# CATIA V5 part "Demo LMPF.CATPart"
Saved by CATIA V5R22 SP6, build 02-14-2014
Part number: Demo AM
Bounding box of the stored display mesh (mm): x -38 to 38, y -38 to 38, z -6.84 to 26.244
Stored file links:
  C:\Users\kremer\Desktop\demo_5x\Demo LMPF.CATPart
  Y:\piece divers\caddy\logo_AM.CATPart
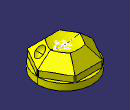
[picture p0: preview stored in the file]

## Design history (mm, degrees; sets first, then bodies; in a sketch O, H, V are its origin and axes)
AxisSystem1: origin (0, 0, 0), X (1, 0, 0), Y (0, 1, 0), Z (0, 0, 1)
Set1
  Plane1: type Angle, RefPlane face of Pocket1 from Sketch2.L1, Direction edge [face of Pocket1 from Sketch2.L1 | end face of Pad1], Angle 45
  Plane2: type Angle, RefPlane face of CircPattern1, Direction Sketch9, Angle 90
  Point1: (0, 0, 80), in AxisSystem1
  Sphere1: Center Point1, Axis AxisSystem1, Radius 57.5, Angle1 -90, Angle3 0, Angle4 360
  MultiSel1
Body1 (main body)
  Sketch1 on XY plane of AxisSystem1, origin (0, 0, 0), H (1, 0, 0), V (0, 1, 0)
    circle A1 centre (0, 0) radius 50
    radius A1 = 50
  Pad1: profile Sketch1, direction (0, 0, 1), length 35, opposite side length 9
  Sketch2 on end face of Pad1, origin (0, 0, 35), H (1, 0, 0), V (0, 1, 0)
    point P1 (25.4034, 44)
    point P2 (-25.4034, 44)
    point P3 (-50.8068, 0)
    point P4 (-25.4034, -44)
    point P5 (25.4034, -44)
    point P6 (50.8068, 0)
    point P7 (0, 44)
    line L1 (25.4034, 44) -> (-25.4034, 44)
    line L2 (-25.4034, 44) -> (-50.8068, 0)
    line L3 (-50.8068, 0) -> (-25.4034, -44)
    line L4 (-25.4034, -44) -> (25.4034, -44)
    line L5 (25.4034, -44) -> (50.8068, 0)
    line L6 (50.8068, 0) -> (25.4034, 44)
    construction line L7 (0, 0) -> (0, 44)
    construction circle A1 centre (0, 0) radius 50.8068
    construction arc A2 centre (25.4034, -44) radius 50.8068 from (-25.4034, -44) to (50.8068, 0) cw
    construction arc A3 centre (-25.4034, 44) radius 50.8068 from (-50.8068, 0) to (25.4034, 44) ccw
    length L7 = 44
    vertical: L7 V
    coincidence: A1 P1, A1 P2, A1 P3, A1 P4, A1 P5, A1 P6, A2 O, A3 O
    midpoint: P7 L1
    parallelism: L1 L4
  Pocket1: profile Sketch2, direction (0, 0, -1), length 32, outer side
  Sketch3 on Plane1, origin (0, 50.6879, 28.3121), H (1, 0, 0), V (0, -0.7071, 0.7071)
    point P1 (0, 7.5)
    line L1 (56.2227, 27) -> (56.2227, -12)
    line L2 (56.2227, -12) -> (-56.2227, -12)
    line L3 (-56.2227, -12) -> (-56.2227, 27)
    line L4 (-56.2227, 27) -> (56.2227, 27)
    distance H L2 = 12
    distance H L4 = 27
    coincidence: P1 V
    vertical: L1 V, L3 V
    horizontal: L2 H, L4 H
    equidistance: L1 L3 P1, L2 L4 P1
  Pocket2: profile Sketch3, direction (0, -0.7071, -0.7071), length 15
  CircPattern1: of Pocket2, instances 6, angular step 60 {= 360.0*1 deg/CircPattern1.AngularNumber}, axis from XY plane of AxisSystem1
  Sketch4 on end face of Pocket2, origin (0, 28.8934, 28.8934), H (-1, 0, 0), V (0, -0.7071, 0.7071)
    circle A1 centre (0, -6.364) radius 11
    point P1 (0, -6.364)
    reference projected line E1 through (0, 0) direction (0, -1) from edge [YZ plane of AxisSystem1 | XY plane of AxisSystem1]
    reference projected line E2 (37.6887, 8.636) -> (-37.6887, 8.636) from edge [end face of Pad1 | end face of Pocket2]
    radius A1 = 11
    distance P1 E2 = 15
    coincidence: P1 E1
  Pocket3: profile Sketch4, direction (0, -0.7071, -0.7071), length 6, deactivated
  Sketch5 on face of CircPattern1, origin (-25.0224, -14.4467, 28.8934), H (0.5, -0.866, 0), V (0.6124, 0.3536, 0.7071)
    line L1 (-8.6038, 0.6201) -> (-11.1038, -3.7101)
    line L2 (8.6599, 0.523) -> (11.1599, -3.8071)
    line L3 (-2.5004, -18.8071) -> (2.4996, -18.8071)
    construction circle A1 centre (0, -7.364) radius 11.4432
    point P7 (0, -7.364)
    arc A2 centre (-0.0004, -4.477) radius 10 from (-8.6038, 0.6201) to (8.6599, 0.523) cw
    arc A3 centre (2.4996, -8.8071) radius 10 from (11.1599, -3.8071) to (2.4996, -18.8071) cw
    arc A4 centre (-2.5004, -8.8071) radius 10 from (-2.5004, -18.8071) to (-11.1038, -3.7101) cw
    reference projected line E1 (-13.156, 8.636) -> (13.156, 8.636) from edge [face of CircPattern1 | end face of Pad1]
    angle L2 L3 = 60
    angle L1 L3 = 60
    length L2 = 5
    length L1 = 5
    length L3 = 5
    radius A2 = 10
    radius A3 = 10
    radius A4 = 10
    distance P7 E1 = 16
    horizontal: L3 H
    tangency: A1 L2, L1 A1, A1 L3, A2 L2, A3 L2, A4 L3
    coincidence: P7 V
  Pocket4: profile Sketch5, direction (0.6124, 0.3536, -0.7071), length 3
  Scaling1: ToTransfor Pocket4, Reference vertex [YZ plane of AxisSystem1 | ZX plane of AxisSystem1 | XY plane of AxisSystem1], Ratio 0.76
  Sketch6 on start face of Pad1, origin (0, 0, -6.84), H (1, 0, 0), V (0, -1, 0)
    circle A1 centre (0, 0) radius 28
    radius A1 = 28
  Pocket5: profile Sketch6, direction (0, 0, 1), length 15
  Sketch7 on YZ plane of AxisSystem1, origin (0, 0, 0), H (0, 1, 0), V (0, 0, 1)
    line L1 (0, -6.84) -> (28, -6.84)
    point P1 (0, -6.84)
    line L2 (0, 8.16) -> (10, 8.16)
    point P3 (0, 8.16)
    arc A1 centre (10, -10.14) radius 18.3 from (28, -6.84) to (10, 8.16) ccw
    axis line L3 (0, 13.16) -> (0, -11.84)
    point P6 (0, 13.16)
    point P7 (0, -11.84)
    reference projected line E1 (-38, -6.84) -> (38, -6.84) from edge [start face of Pad1 | face of Pad1 from Sketch1.A1]
    length L1 = 28
    length L2 = 10
    distance L2 L1 = 15
    distance P7 L1 = 5
    distance P6 L2 = 5
    coincidence: P1 V, P3 V, P6 V, L1 E1
    horizontal: L1 H, L2 H
    tangency: A1 L2
    vertical: L3 V
  Groove1: profile Sketch7, axis Sketch7.L3, angle 360
  Sketch8 on Plane2, origin (3.2068, -1.8514, -3.7028), H (-0.5, -0.866, 0), V (0.6124, -0.3536, 0.7071)
    arc A1 centre (0, 33.0547) radius 8 from (0, 25.0547) to (7.746, 31.0547) ccw
    point P1 (0, 33.0547)
    point P2 (0, 25.0547)
    point P3 (7.746, 31.0547)
    axis line L1 (0, 14.857) -> (0, 47.7135)
    point P4 (0, 14.857)
    reference projected line E1 (-9.9985, 31.0547) -> (9.9985, 31.0547) from edge [end face of Pad1 | face of CircPattern1]
    reference projected line E2 (-9.9985, 31.0547) -> (9.9985, 31.0547) from edge [end face of Pad1 | face of CircPattern1]
    radius A1 = 8
    distance P1 E2 = 2
    coincidence: P1 V, P2 V, P4 V, P3 E1
    vertical: L1 V
  Groove2: profile Sketch8, axis Sketch8.L1, angle 360
  Sketch9 "( Axe Ref 1 ) Esquisse.30" on face of CircPattern1, origin (19.017, -10.9795, 21.959), H (0.5, 0.866, 0), V (-0.6124, 0.3536, 0.7071)
    line L1 (-58.589, -5.2366) -> (57.1551, -5.2366)
    reference projected line E1 (-18.049, -16.2366) -> (18.049, -16.2366) from edge [face of Pocket1 from Sketch2.L5 | face of CircPattern1]
    distance L1 E1 = 11
    horizontal: L1 H
  Split1: SplitPlane Sphere1
  Sketch10 "AM_contour ext" on xy-plane, origin (4.33, 0, 0), H (0, 1, 0), V (-1, 0, 0)
    construction line L1 (0, 60.7322) -> (0, -11.7377)
    point P17 (3.4248, 5.9688)
    point P19 (0, 15.8119)
    arc A1 centre (59.4869, -14.2774) radius 60.2195 from (0, -4.9132) to (1.5177, 2.0306) cw
    arc A2 centre (9.7654, 7.017) radius 9.6379 from (1.5177, 2.0306) to (5.3889, -1.5699) ccw
    arc A3 centre (-14.9238, 4.3682) radius 21.1629 from (5.3889, -1.5699) to (3.6441, -5.7856) cw
    arc A4 centre (-23.671, 8.3459) radius 31.4277 from (6.0559, -1.8526) to (4.0351, -6.489) cw
    spline S1 through (3.6458, -5.7858) (3.5931, -5.7699) (3.4911, -5.6186) (3.1628, -5.286) (2.82, -5.2669) (2.3716, -5.4882) (2.1874, -5.8327) (2.1242, -6.4187) (2.252, -6.8572) (2.4958, -7.1703) (2.7571, -7.3255) (3.1036, -7.3604) (3.4777, -7.1797) (3.823, -6.8205) (4.0351, -6.489)
    arc A5 centre (6.6749, 1.3247) radius 3.237 from (6.0559, -1.8526) to (9.9071, 1.5021) ccw
    spline S2 through (9.9065, 1.5017) (9.6533, 2.299) (8.894, 2.8422) (8.0588, 2.7385) (7.695, 2.4017) (7.379, 1.5027) (7.7109, 0.6261) (8.2591, 0.2442) (8.6579, 0.2441)
    arc A6 centre (-6.6766, 2.7131) radius 13.278 from (6.2511, -0.3165) to (5.5057, 7.9947) ccw
    arc A7 centre (9.9792, 2.4699) radius 8.4343 from (1.8858, 4.8435) to (3.5816, 7.9661) cw
    spline S3 through (3.5816, 7.9661) (3.8645, 8.2339) (4.3523, 8.4727) (4.7949, 8.4722) (5.303, 8.2673) (5.5057, 7.9947)
    arc A8 centre (39.3291, 16.8757) radius 39.3291 from (0, 16.8757) to (1.8858, 4.8435) ccw
    spline S4 through (6.2511, -0.3165) (6.5819, -0.417) (7.0252, -0.5357) (7.4685, -0.6005) (7.9983, -0.6005) (8.3767, -0.4817) (8.5713, -0.2118) (8.6795, 0.1229) (8.6579, 0.2441)
    point P21 (0, -4.5)
    construction line L2 through (0, 0) direction (-1, 0)
    construction line L3 through (0, 0) direction (0, 1)
    point P22 (0, -11.7377)
    point P23 (0, 16.8757)
    point P24 (0, 15.8119)
    point P25 (0, -4.5)
    construction line L4 through (0, 0) direction (-1, 0)
    construction line L5 through (0, 0) direction (0, 1)
    point P26 (0, -11.7377)
    point P41 (-3.4248, 5.9688)
    point P43 (0, 15.8119)
    point P44 (0, -4.5)
    point P45 (0, -11.7377)
    point P46 (0, 16.8757)
    point P47 (0, 15.8119)
    arc A9 centre (-59.4869, -14.2774) radius 60.2195 from (0, -4.9132) to (-1.5177, 2.0306) ccw
    arc A10 centre (-9.7654, 7.017) radius 9.6379 from (-1.5177, 2.0306) to (-5.3889, -1.5699) cw
    arc A11 centre (14.9238, 4.3682) radius 21.1629 from (-5.3889, -1.5699) to (-3.6441, -5.7856) ccw
    arc A12 centre (23.671, 8.3459) radius 31.4277 from (-6.0559, -1.8526) to (-4.0351, -6.489) ccw
    spline S5 through (-3.6458, -5.7858) (-3.5931, -5.7699) (-3.4911, -5.6186) (-3.1628, -5.286) (-2.82, -5.2669) (-2.3716, -5.4882) (-2.1874, -5.8327) (-2.1242, -6.4187) (-2.252, -6.8572) (-2.4958, -7.1703) (-2.7571, -7.3255) (-3.1036, -7.3604) (-3.4777, -7.1797) (-3.823, -6.8205) (-4.0351, -6.489)
    arc A13 centre (-6.6749, 1.3247) radius 3.237 from (-6.0559, -1.8526) to (-9.9071, 1.5021) cw
    spline S6 through (-9.9065, 1.5017) (-9.6533, 2.299) (-8.894, 2.8422) (-8.0588, 2.7385) (-7.695, 2.4017) (-7.379, 1.5027) (-7.7109, 0.6261) (-8.2591, 0.2442) (-8.659, 0.244)
    arc A14 centre (6.6766, 2.7131) radius 13.278 from (-6.2511, -0.3165) to (-5.5057, 7.9947) cw
    arc A15 centre (-9.9792, 2.4699) radius 8.4343 from (-1.8858, 4.8435) to (-3.5816, 7.9661) ccw
    spline S7 through (-3.5816, 7.9661) (-3.8645, 8.2339) (-4.3523, 8.4727) (-4.7949, 8.4722) (-5.303, 8.2673) (-5.5057, 7.9947)
    arc A16 centre (-39.3291, 16.8757) radius 39.3291 from (0, 16.8757) to (-1.8858, 4.8435) cw
    spline S8 through (-6.2511, -0.3165) (-6.5819, -0.417) (-7.0252, -0.5357) (-7.4685, -0.6005) (-7.9983, -0.6005) (-8.3767, -0.4817) (-8.5713, -0.2118) (-8.6795, 0.1229) (-8.659, 0.244)
    point P64 (8.6579, 0.2441)
    point P79 (8.6579, 0.2441)
    point P103 (-8.659, 0.244)
    point P118 (-8.659, 0.244)
    symmetry: H L2 L1, V L3 L1, H L4 L3, V L5 L3
    tangency: A6 S3, S3 A7
    coincidence: P118 P103, P64 P79
  Sketch11 "AM_central" on xy-plane, origin (4.33, 0, 0), H (0, 1, 0), V (-1, 0, 0)
    construction line L1 (0, 60.7322) -> (0, -11.7377)
    point P6 (0, 15.8119)
    arc A1 centre (29.0923, -5.4555) radius 29.4289 from (0, -1.0173) to (0.9488, 3.147) cw
    arc A2 centre (25.6801, 11.3678) radius 26.0618 from (0.9488, 3.147) to (0, 6.9237) cw
    point P7 (0, -4.5)
    construction line L2 through (0, 0) direction (-1, 0)
    construction line L3 through (0, 0) direction (0, 1)
    point P8 (0, -11.7377)
    point P9 (0, 16.8757)
    point P10 (0, 15.8119)
    point P11 (0, -4.5)
    construction line L4 through (0, 0) direction (-1, 0)
    construction line L5 through (0, 0) direction (0, 1)
    point P12 (0, -11.7377)
    point P13 (-5.0293, 6.1577)
    point P17 (0, 15.8119)
    point P18 (0, -4.5)
    point P19 (0, -11.7377)
    point P20 (0, 16.8757)
    point P21 (0, 15.8119)
    arc A3 centre (-29.0923, -5.4555) radius 29.4289 from (0, -1.0173) to (-0.9488, 3.147) ccw
    arc A4 centre (-25.6801, 11.3678) radius 26.0618 from (-0.9488, 3.147) to (0, 6.9237) ccw
    symmetry: H L2 L1, V L3 L1, H L4 L3, V L5 L3
  Sketch12 "AM_bas" on xy-plane, origin (4.33, 0, 0), H (0, 1, 0), V (-1, 0, 0)
    construction line L1 (0, 60.7322) -> (0, -11.7377)
    line L2 (0, -11.7951) -> (2.0186, -9.3913)
    arc A1 centre (-0.9566, -8.5776) radius 1.6694 from (0, -9.9457) to (0.7051, -8.7379) ccw
    arc A2 centre (1.8578, -8.0675) radius 1.3335 from (0.7051, -8.7379) to (2.0186, -9.3913) ccw
    construction line L3 through (0, 0) direction (-1, 0)
    construction line L4 through (0, 0) direction (0, 1)
    point P9 (0, -11.7377)
    construction line L5 through (0, 0) direction (0, 1)
    point P10 (0, -11.7377)
    point P17 (0, -11.7377)
    line L6 (0, -11.7951) -> (-2.0186, -9.3913)
    arc A3 centre (0.9566, -8.5776) radius 1.6694 from (0, -9.9457) to (-0.7051, -8.7379) cw
    arc A4 centre (-1.8578, -8.0675) radius 1.3335 from (-0.7051, -8.7379) to (-2.0186, -9.3913) cw
  Sketch13 "AM_cplt" on xy-plane, origin (4.33, 0, 0), H (0, 1, 0), V (-1, 0, 0)
    construction line L1 (0, 60.7322) -> (0, -11.7377)
    point P33 (0, 15.8119)
    line L2 (0, -11.7951) -> (2.0186, -9.3913)
    arc A1 centre (-0.9566, -8.5776) radius 1.6694 from (0, -9.9457) to (0.7051, -8.7379) ccw
    arc A2 centre (1.8578, -8.0675) radius 1.3335 from (0.7051, -8.7379) to (2.0186, -9.3913) ccw
    arc A3 centre (59.4869, -14.2774) radius 60.2195 from (0, -4.9132) to (1.5177, 2.0306) cw
    arc A4 centre (9.7654, 7.017) radius 9.6379 from (1.5177, 2.0306) to (5.3889, -1.5699) ccw
    arc A5 centre (-14.9238, 4.3682) radius 21.1629 from (5.3889, -1.5699) to (3.6441, -5.7856) cw
    arc A6 centre (-23.671, 8.3459) radius 31.4277 from (6.0559, -1.8526) to (4.0351, -6.489) cw
    spline S1 through (3.6458, -5.7858) (3.5931, -5.7699) (3.4911, -5.6186) (3.1628, -5.286) (2.82, -5.2669) (2.3716, -5.4882) (2.1874, -5.8327) (2.1242, -6.4187) (2.252, -6.8572) (2.4958, -7.1703) (2.7571, -7.3255) (3.1036, -7.3604) (3.4777, -7.1797) (3.823, -6.8205) (4.0351, -6.489)
    arc A7 centre (6.6749, 1.3247) radius 3.237 from (6.0559, -1.8526) to (9.9071, 1.5021) ccw
    spline S2 through (9.9065, 1.5017) (9.6533, 2.299) (8.894, 2.8422) (8.0588, 2.7385) (7.695, 2.4017) (7.379, 1.5027) (7.7109, 0.6261) (8.2591, 0.2442) (8.6579, 0.2441)
    arc A8 centre (-6.6766, 2.7131) radius 13.278 from (6.2511, -0.3165) to (5.5057, 7.9947) ccw
    arc A9 centre (9.9792, 2.4699) radius 8.4343 from (1.8858, 4.8435) to (3.5816, 7.9661) cw
    spline S3 through (3.5816, 7.9661) (3.8645, 8.2339) (4.3523, 8.4727) (4.7949, 8.4722) (5.303, 8.2673) (5.5057, 7.9947)
    arc A10 centre (39.3291, 16.8757) radius 39.3291 from (0, 16.8757) to (1.8858, 4.8435) ccw
    spline S4 through (6.2511, -0.3165) (6.5819, -0.417) (7.0252, -0.5357) (7.4685, -0.6005) (7.9983, -0.6005) (8.3767, -0.4817) (8.5713, -0.2118) (8.6795, 0.1229) (8.659, 0.244)
    arc A11 centre (9.5716, 6.3023) radius 7.4668 from (2.5819, 3.6763) to (5.7001, -0.0823) ccw
    arc A12 centre (7.8975, 3.0231) radius 5.3556 from (2.5819, 3.6763) to (3.4248, 5.9688) cw
    arc A13 centre (-2.0857, 2.2369) radius 8.1238 from (5.7001, -0.0823) to (5.0293, 6.1577) ccw
    arc A14 centre (29.0923, -5.4555) radius 29.4289 from (0, -1.0173) to (0.9488, 3.147) cw
    arc A15 centre (25.6801, 11.3678) radius 26.0618 from (0.9488, 3.147) to (0, 6.9237) cw
    point P35 (0, -4.5)
    construction line L3 through (0, 0) direction (-1, 0)
    construction line L4 through (0, 0) direction (0, 1)
    point P36 (0, -11.7377)
    point P37 (0, 16.8757)
    point P38 (0, 15.8119)
    connectcurve C1
    point P39 (0, -4.5)
    construction line L5 through (0, 0) direction (-1, 0)
    construction line L6 through (0, 0) direction (0, 1)
    point P40 (0, -11.7377)
    point P71 (0, 15.8119)
    point P72 (0, -4.5)
    point P73 (0, -11.7377)
    point P74 (0, 16.8757)
    point P75 (0, 15.8119)
    line L7 (0, -11.7951) -> (-2.0186, -9.3913)
    arc A16 centre (0.9566, -8.5776) radius 1.6694 from (0, -9.9457) to (-0.7051, -8.7379) cw
    arc A17 centre (-1.8578, -8.0675) radius 1.3335 from (-0.7051, -8.7379) to (-2.0186, -9.3913) cw
    arc A18 centre (-59.4869, -14.2774) radius 60.2195 from (0, -4.9132) to (-1.5177, 2.0306) ccw
    arc A19 centre (-9.7654, 7.017) radius 9.6379 from (-1.5177, 2.0306) to (-5.3889, -1.5699) cw
    arc A20 centre (14.9238, 4.3682) radius 21.1629 from (-5.3889, -1.5699) to (-3.6441, -5.7856) ccw
    arc A21 centre (23.671, 8.3459) radius 31.4277 from (-6.0559, -1.8526) to (-4.0351, -6.489) ccw
    spline S5 through (-3.6458, -5.7858) (-3.5931, -5.7699) (-3.4911, -5.6186) (-3.1628, -5.286) (-2.82, -5.2669) (-2.3716, -5.4882) (-2.1874, -5.8327) (-2.1242, -6.4187) (-2.252, -6.8572) (-2.4958, -7.1703) (-2.7571, -7.3255) (-3.1036, -7.3604) (-3.4777, -7.1797) (-3.823, -6.8205) (-4.0351, -6.489)
    arc A22 centre (-6.6749, 1.3247) radius 3.237 from (-6.0559, -1.8526) to (-9.9071, 1.5021) cw
    spline S6 through (-9.9065, 1.5017) (-9.6533, 2.299) (-8.894, 2.8422) (-8.0588, 2.7385) (-7.695, 2.4017) (-7.379, 1.5027) (-7.7109, 0.6261) (-8.2591, 0.2442) (-8.6579, 0.2441)
    arc A23 centre (6.6766, 2.7131) radius 13.278 from (-6.2511, -0.3165) to (-5.5057, 7.9947) cw
    arc A24 centre (-9.9792, 2.4699) radius 8.4343 from (-1.8858, 4.8435) to (-3.5816, 7.9661) ccw
    spline S7 through (-3.5816, 7.9661) (-3.8645, 8.2339) (-4.3523, 8.4727) (-4.7949, 8.4722) (-5.303, 8.2673) (-5.5057, 7.9947)
    arc A25 centre (-39.3291, 16.8757) radius 39.3291 from (0, 16.8757) to (-1.8858, 4.8435) cw
    spline S8 through (-6.2511, -0.3165) (-6.5819, -0.417) (-7.0252, -0.5357) (-7.4685, -0.6005) (-7.9983, -0.6005) (-8.3767, -0.4817) (-8.5713, -0.2118) (-8.6795, 0.1229) (-8.659, 0.244)
    arc A26 centre (-9.5716, 6.3023) radius 7.4668 from (-2.5819, 3.6763) to (-5.7001, -0.0823) cw
    arc A27 centre (-7.8975, 3.0231) radius 5.3556 from (-2.5819, 3.6763) to (-3.4248, 5.9688) ccw
    arc A28 centre (2.0857, 2.2369) radius 8.1238 from (-5.7001, -0.0823) to (-5.0293, 6.1577) cw
    arc A29 centre (-29.0923, -5.4555) radius 29.4289 from (0, -1.0173) to (-0.9488, 3.147) ccw
    arc A30 centre (-25.6801, 11.3678) radius 26.0618 from (-0.9488, 3.147) to (0, 6.9237) ccw
    connectcurve C2
    symmetry: H L3 L1, V L4 L1, H L5 L4, V L6 L4
    tangency: A8 S3, S3 A9
  Sketch14 "AM_g" on xy-plane, origin (4.33, 0, 0), H (0, 1, 0), V (-1, 0, 0)
    point P1 (0, 15.8119)
    construction line L1 through (0, 0) direction (-1, 0)
    construction line L2 through (0, 0) direction (0, 1)
    point P2 (0, 16.8757)
    point P3 (0, 15.8119)
    construction line L3 through (0, 0) direction (0, 1)
    point P8 (0, 15.8119)
    point P9 (0, 16.8757)
    point P10 (0, 15.8119)
    arc A1 centre (-9.5716, 6.3023) radius 7.4668 from (-2.5819, 3.6763) to (-5.7001, -0.0823) cw
    arc A2 centre (-7.8975, 3.0231) radius 5.3556 from (-2.5819, 3.6763) to (-3.4248, 5.9688) ccw
    arc A3 centre (2.0857, 2.2369) radius 8.1238 from (-5.7001, -0.0823) to (-5.0293, 6.1577) cw
    connectcurve C1
    symmetry: V L3 L2
  Sketch15 "AM_d" on xy-plane, origin (4.33, 0, 0), H (0, 1, 0), V (-1, 0, 0)
    point P5 (0, 15.8119)
    arc A1 centre (9.5716, 6.3023) radius 7.4668 from (2.5819, 3.6763) to (5.7001, -0.0823) ccw
    arc A2 centre (7.8975, 3.0231) radius 5.3556 from (2.5819, 3.6763) to (3.4248, 5.9688) cw
    arc A3 centre (-2.0857, 2.2369) radius 8.1238 from (5.7001, -0.0823) to (5.0293, 6.1577) ccw
    point P6 (0, -4.5)
    construction line L1 through (0, 0) direction (-1, 0)
    construction line L2 through (0, 0) direction (0, 1)
    point P7 (0, 16.8757)
    point P8 (0, 15.8119)
    connectcurve C1
    point P9 (0, -4.5)
    construction line L3 through (0, 0) direction (0, 1)
    point P10 (0, 15.8119)
    point P11 (0, -4.5)
    point P12 (0, 16.8757)
    point P13 (0, 15.8119)
    symmetry: V L3 L2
